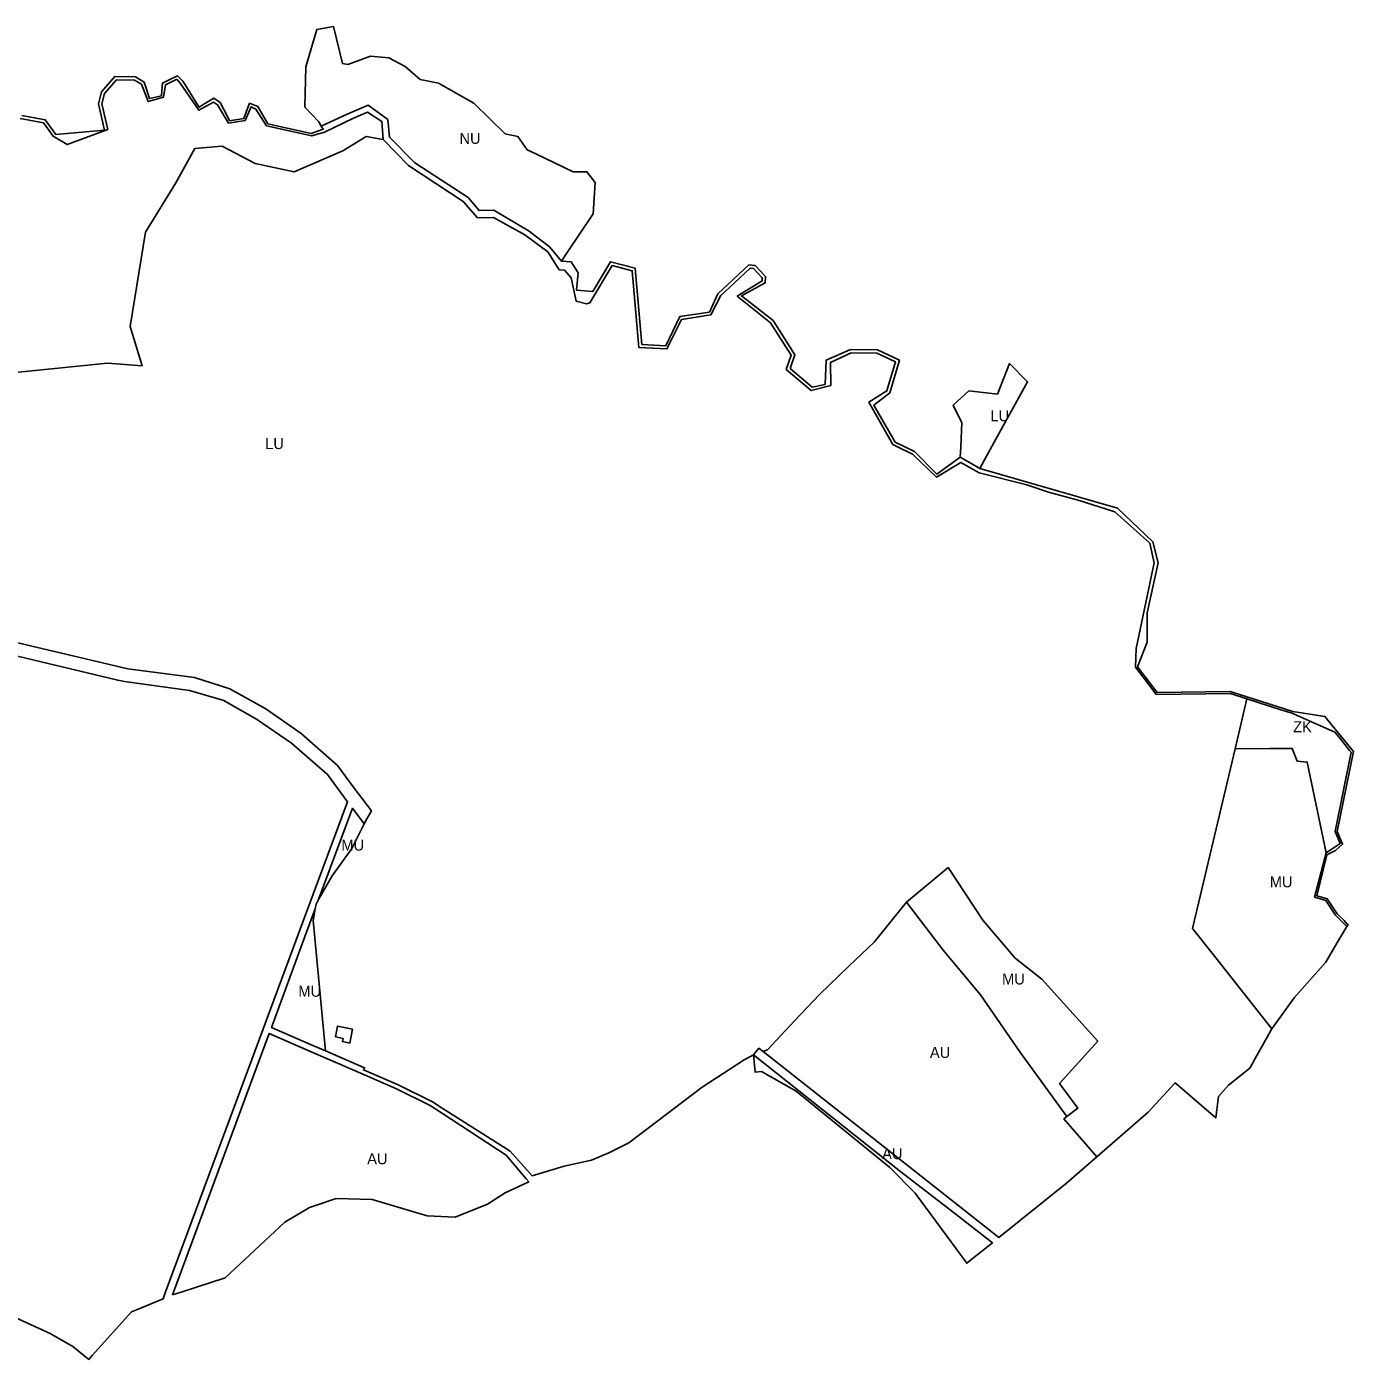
# Model space of a CAD drawing. Extents: x -522079 to -518833, y -1142398 to -1139961.
# Drawn here: x -519439 to -518833, y -1141872 to -1141262 of the extents above; entities that cross this region are included whole.
import ezdxf

# ---------------------------------------------------------------- set-up
doc = ezdxf.new("R2010")
doc.units = 0
for name, color, linetype in [('90640013', 7, 'Continuous'), ('90710013', 7, 'Continuous'), ('90730013', 7, 'Continuous'), ('90750013', 7, 'Continuous'), ('90770013', 7, 'Continuous'), ('90830013', 7, 'Continuous')]:
    doc.layers.add(name, color=color, linetype=linetype)

msp = doc.modelspace()

# ---------------------------------------------------------------- linework, layer by layer
at = {"layer": '90640013'}
msp.add_lwpolyline([(-519441.7, -1141302.87), (-519430.99, -1141304.77), (-519426.16, -1141311.48), (-519403.83, -1141309.49), (-519406.68, -1141297.5), (-519405.2, -1141292.02), (-519399.13, -1141285.07), (-519389.78, -1141285.13), (-519385.69, -1141287.55), (-519385.12, -1141289.38), (-519383.31, -1141295.11), (-519377.88, -1141293.85), (-519377.66, -1141291.53), (-519377.33, -1141288.06), (-519373.33, -1141286.11), (-519370.55, -1141284.76), (-519368.04, -1141287.17), (-519367.51, -1141288.01), (-519361.74, -1141297.24), (-519360.6, -1141299.07), (-519359.18, -1141298.18), (-519353.95, -1141294.93), (-519351.06, -1141296.96), (-519347.55, -1141303.63), (-519346.7, -1141305.23), (-519340.12, -1141304.19), (-519339.07, -1141301.4), (-519337.51, -1141297.26), (-519333.7, -1141298.67), (-519329.18, -1141306.68), (-519309.3, -1141311.02), (-519303.86, -1141309.05), (-519304.74, -1141307.68), (-519292.93, -1141302.27), (-519283.38, -1141298.07), (-519274.28, -1141304.73), (-519273.62, -1141312.83), (-519261.98, -1141324.54), (-519255.87, -1141328.5), (-519237.64, -1141340.3), (-519232.62, -1141346.31), (-519225.91, -1141346.11), (-519209.66, -1141355.81), (-519200.4, -1141362.91), (-519194.96, -1141369.43), (-519190.42, -1141369.81), (-519187.2, -1141374.82), (-519188.01, -1141382.78), (-519180.54, -1141383.29), (-519172.49, -1141369.75), (-519161.16, -1141372.68), (-519158.19, -1141407.51), (-519147.23, -1141408.12), (-519140.85, -1141394.82), (-519127.25, -1141392.73), (-519123.4, -1141384.39), (-519109.18, -1141371.2), (-519106.36, -1141371.37), (-519101.55, -1141376.47), (-519101.7, -1141379.43), (-519112.59, -1141385.36), (-519098.12, -1141396.65), (-519088.18, -1141412.32), (-519090.32, -1141418.48), (-519080.26, -1141427.02), (-519074.35, -1141425.83), (-519073.85, -1141414.66), (-519062.78, -1141409.81), (-519050.33, -1141409.98), (-519040.39, -1141414.74), (-519044.82, -1141429.69), (-519052, -1141435.32), (-519042.3, -1141452.19), (-519033.46, -1141456.53), (-519023.29, -1141466.86), (-519012.53, -1141459.04), (-519005.83, -1141462.95), (-519003.59, -1141464.2), (-518940.71, -1141482.48), (-518924.49, -1141497.8), (-518922.06, -1141507.35), (-518927.02, -1141530.23), (-518927.11, -1141543.74), (-518931.43, -1141555), (-518922.51, -1141566.63), (-518889.18, -1141566.18), (-518860.53, -1141575.36), (-518845.76, -1141577.71), (-518832.78, -1141593.74), (-518840.17, -1141630.23), (-518837.74, -1141636.08), (-518840.9, -1141638.87), (-518844.96, -1141640.98), (-518849.41, -1141659.71), (-518844.75, -1141661.05), (-518840.16, -1141667.91), (-518837.05, -1141671.02), (-518835.83, -1141672.48), (-518835.18, -1141672.79), (-518835.69, -1141673.66), (-518840.87, -1141668.48), (-518845.32, -1141661.82), (-518850.48, -1141660.34), (-518845.18, -1141639.97), (-518838.85, -1141635.75), (-518841.11, -1141630.32), (-518833.75, -1141593.98), (-518834.47, -1141593.24), (-518839.43, -1141586.95), (-518841.19, -1141584.77), (-518858.5, -1141577.22), (-518860.8, -1141576.22), (-518865.88, -1141574.59), (-518881.49, -1141569.59), (-518888.92, -1141567.21), (-518922.95, -1141567.54), (-518924.52, -1141565.49), (-518932.45, -1141555.15), (-518932.13, -1141546.59), (-518923.9, -1141507.34), (-518925.88, -1141498.42), (-518941.87, -1141484.11), (-518958.68, -1141478.71), (-518972.22, -1141475.1), (-518982.13, -1141471.67), (-519003.93, -1141466.26), (-519012.3, -1141461.46), (-519023.36, -1141468.17), (-519034.35, -1141457.76), (-519041.21, -1141454.39), (-519043.38, -1141453.33), (-519054.33, -1141433.88), (-519046.13, -1141428.81), (-519042.19, -1141415.54), (-519048.65, -1141412.42), (-519050.68, -1141411.48), (-519062.49, -1141411.31), (-519071.92, -1141415.76), (-519071.77, -1141426.39), (-519080.67, -1141428.64), (-519092.08, -1141418.96), (-519089.83, -1141412.51), (-519099.25, -1141397.67), (-519114.56, -1141385.44), (-519103.16, -1141378.52), (-519103.08, -1141377.03), (-519107.04, -1141372.83), (-519108.63, -1141372.74), (-519115.78, -1141379.37), (-519122.09, -1141385.22), (-519126.66, -1141393.95), (-519140.08, -1141396.13), (-519146.7, -1141409.56), (-519159.57, -1141408.94), (-519162.56, -1141373.86), (-519171.77, -1141371.48), (-519181.87, -1141388.46), (-519183.39, -1141388.93), (-519188.19, -1141387.74), (-519190.53, -1141377.07), (-519193.48, -1141373.59), (-519195.98, -1141373.38), (-519201.22, -1141365.24), (-519211.68, -1141357.48), (-519225.95, -1141349.55), (-519233.32, -1141349.64), (-519239.84, -1141342.13), (-519264.89, -1141325.79), (-519276.42, -1141313.78), (-519277.01, -1141305.57), (-519283.62, -1141301.34), (-519290.01, -1141304.08), (-519303.35, -1141310.46), (-519309.12, -1141312.18), (-519329.81, -1141307.56), (-519334.73, -1141299.89), (-519336.85, -1141298.85), (-519339.54, -1141305.07), (-519347.17, -1141306.35), (-519352.22, -1141297.98), (-519354, -1141296.72), (-519360.8, -1141300.45), (-519369.21, -1141288.13), (-519370.85, -1141286.3), (-519376.04, -1141288.86), (-519376.93, -1141294.5), (-519383.98, -1141296.49), (-519386.96, -1141288.54), (-519390.2, -1141286.63), (-519398.45, -1141286.57), (-519403.84, -1141292.74), (-519405.13, -1141297.52), (-519402.36, -1141309.19), (-519420.99, -1141316.12), (-519427.38, -1141312.36), (-519431.85, -1141306.14), (-519442.41, -1141304.27)], dxfattribs=at)
at = {"layer": '90710013'}
msp.add_lwpolyline([(-518845.18, -1141639.97), (-518853.84, -1141598.54), (-518858.42, -1141598.04), (-518860.72, -1141592.27), (-518870.9, -1141592.32), (-518886.88, -1141592.39), (-518881.49, -1141569.59), (-518865.88, -1141574.59), (-518860.8, -1141576.22), (-518858.5, -1141577.22), (-518841.19, -1141584.77), (-518839.43, -1141586.95), (-518834.47, -1141593.24), (-518833.75, -1141593.98), (-518841.11, -1141630.32), (-518838.85, -1141635.75)], close=True, dxfattribs=at)
at = {"layer": '90730013'}
msp.add_lwpolyline([(-519304.74, -1141307.68), (-519305.93, -1141305.82), (-519312.28, -1141299.01), (-519311.83, -1141280.54), (-519306.82, -1141263.47), (-519299.19, -1141262.23), (-519295.1, -1141279.15), (-519292.59, -1141279.53), (-519282.24, -1141275.71), (-519273.89, -1141276.5), (-519266.36, -1141280.43), (-519259.58, -1141286.33), (-519251.16, -1141288.07), (-519234.97, -1141297.23), (-519220.59, -1141311.22), (-519214.82, -1141312.52), (-519210.53, -1141318.6), (-519206.65, -1141320.44), (-519189.49, -1141328.56), (-519183.26, -1141328.59), (-519179.55, -1141333.52), (-519180.48, -1141347.87), (-519192.3, -1141365.49), (-519194.96, -1141369.43), (-519200.4, -1141362.91), (-519209.66, -1141355.81), (-519225.91, -1141346.11), (-519232.62, -1141346.31), (-519237.64, -1141340.3), (-519255.87, -1141328.5), (-519261.98, -1141324.54), (-519273.62, -1141312.83), (-519274.28, -1141304.73), (-519283.38, -1141298.07), (-519292.93, -1141302.27)], close=True, dxfattribs=at)
msp.add_lwpolyline([(-519442.41, -1141304.27), (-519431.85, -1141306.14), (-519427.38, -1141312.36), (-519420.99, -1141316.12), (-519402.36, -1141309.19), (-519405.13, -1141297.52), (-519403.84, -1141292.74), (-519398.45, -1141286.57), (-519390.2, -1141286.63), (-519386.96, -1141288.54), (-519383.98, -1141296.49), (-519376.93, -1141294.5), (-519376.04, -1141288.86), (-519370.85, -1141286.3), (-519369.21, -1141288.13), (-519360.8, -1141300.45), (-519354, -1141296.72), (-519352.22, -1141297.98), (-519347.17, -1141306.35), (-519339.54, -1141305.07), (-519336.85, -1141298.85), (-519334.73, -1141299.89), (-519329.81, -1141307.56), (-519309.12, -1141312.18), (-519303.35, -1141310.46), (-519290.01, -1141304.08), (-519283.62, -1141301.34), (-519277.01, -1141305.57), (-519276.42, -1141313.78), (-519284.21, -1141312.41), (-519294.89, -1141319.05), (-519317.19, -1141328.69), (-519334.98, -1141324.76), (-519350.02, -1141316.82), (-519362.63, -1141317.99), (-519371.28, -1141333.68), (-519385.2, -1141356.16), (-519392.16, -1141399.31), (-519386.73, -1141417.35), (-519402.53, -1141416.1), (-519450.75, -1141420.94)], dxfattribs=at)
at = {"layer": '90750013'}
msp.add_lwpolyline([(-519464.89, -1141545.09), (-519397.82, -1141561.07), (-519394.67, -1141561.74), (-519364.95, -1141565.79), (-519349.35, -1141570.28), (-519346.66, -1141571.83), (-519334.38, -1141578.92), (-519318.43, -1141589.84), (-519301.98, -1141604.24), (-519292.71, -1141616.64), (-519312.84, -1141670.86), (-519336.47, -1141734.52), (-519376.07, -1141841.19), (-519377.1, -1141843.96), (-519389.29, -1141849.01), (-519391.5, -1141849.93), (-519408.1, -1141868.36), (-519409.46, -1141869.87), (-519411.05, -1141871.62), (-519418.41, -1141865.69), (-519428.71, -1141859.77), (-519471.59, -1141840.28)], dxfattribs=at)
for points in [[(-519037.2, -1141662.52), (-519020.32, -1141684.47), (-519003.26, -1141704.92), (-518985.35, -1141731.05), (-518963.82, -1141760.65), (-518965.15, -1141761.66), (-518950.14, -1141779.05), (-518963.91, -1141791), (-518994.87, -1141815.89), (-519013.82, -1141800.95), (-519102.66, -1141730.9), (-519100.73, -1141730.04), (-519088.31, -1141716.77), (-519076.93, -1141704.76), (-519063.3, -1141691.75), (-519051.93, -1141680.89)], [(-519372.86, -1141842.19), (-519371.92, -1141839.65), (-519336.07, -1141742.78), (-519328.61, -1141722.63), (-519309.44, -1141730.94), (-519289.52, -1141739.58), (-519270.39, -1141747.88), (-519254.9, -1141755.61), (-519249.34, -1141759.14), (-519220.27, -1141778.33), (-519211, -1141789.08), (-519209.88, -1141790.38), (-519220.64, -1141795.43), (-519228.74, -1141800.67), (-519243.51, -1141806.68), (-519256.37, -1141806.05), (-519281.47, -1141798.57), (-519297.93, -1141798.04), (-519308.25, -1141801.56), (-519310.14, -1141802.21), (-519316.53, -1141805.97), (-519321.4, -1141808.82), (-519348.63, -1141834.32), (-519368.78, -1141840.86)], [(-519107.07, -1141732.42), (-519039.72, -1141785.92), (-519017.2, -1141803.32), (-518997.83, -1141818.27), (-519007.06, -1141825.69), (-519009.58, -1141827.71), (-519033.21, -1141795.69), (-519044.72, -1141783.93), (-519087.6, -1141748.94), (-519103.5, -1141739.96), (-519106.29, -1141740.33)]]:
    msp.add_lwpolyline(points, close=True, dxfattribs=at)
at = {"layer": '90770013'}
msp.add_lwpolyline([(-519450.75, -1141420.94), (-519402.53, -1141416.1), (-519386.73, -1141417.35), (-519392.16, -1141399.31), (-519385.2, -1141356.16), (-519371.28, -1141333.68), (-519362.63, -1141317.99), (-519350.02, -1141316.82), (-519334.98, -1141324.76), (-519317.19, -1141328.69), (-519294.89, -1141319.05), (-519284.21, -1141312.41), (-519276.42, -1141313.78), (-519264.89, -1141325.79), (-519239.84, -1141342.13), (-519233.32, -1141349.64), (-519225.95, -1141349.55), (-519211.68, -1141357.48), (-519201.22, -1141365.24), (-519195.98, -1141373.38), (-519193.48, -1141373.59), (-519190.53, -1141377.07), (-519188.19, -1141387.74), (-519183.39, -1141388.93), (-519181.87, -1141388.46), (-519171.77, -1141371.48), (-519162.56, -1141373.86), (-519159.57, -1141408.94), (-519146.7, -1141409.56), (-519140.08, -1141396.13), (-519126.66, -1141393.95), (-519122.09, -1141385.22), (-519115.78, -1141379.37), (-519108.63, -1141372.74), (-519107.04, -1141372.83), (-519103.08, -1141377.03), (-519103.16, -1141378.52), (-519114.56, -1141385.44), (-519099.25, -1141397.67), (-519089.83, -1141412.51), (-519092.08, -1141418.96), (-519080.67, -1141428.64), (-519071.77, -1141426.39), (-519071.92, -1141415.76), (-519062.49, -1141411.31), (-519050.68, -1141411.48), (-519048.65, -1141412.42), (-519042.19, -1141415.54), (-519046.13, -1141428.81), (-519054.33, -1141433.88), (-519043.38, -1141453.33), (-519041.21, -1141454.39), (-519034.35, -1141457.76), (-519023.36, -1141468.17), (-519012.3, -1141461.46), (-519003.93, -1141466.26), (-518982.13, -1141471.67), (-518972.22, -1141475.1), (-518958.68, -1141478.71), (-518941.87, -1141484.11), (-518925.88, -1141498.42), (-518923.9, -1141507.34), (-518932.13, -1141546.59), (-518932.45, -1141555.15), (-518924.52, -1141565.49), (-518922.95, -1141567.54), (-518888.92, -1141567.21), (-518881.49, -1141569.59), (-518886.88, -1141592.39), (-518906.3, -1141674.57), (-518897.41, -1141685.82), (-518869.99, -1141720.5), (-518876.08, -1141731.29), (-518880.1, -1141738.42), (-518889.83, -1141746.28), (-518894.38, -1141751.49), (-518895.73, -1141761.19), (-518914.26, -1141745.22), (-518926.6, -1141758.63), (-518950.14, -1141779.05), (-518965.15, -1141761.66), (-518963.82, -1141760.65), (-518958.75, -1141756.79), (-518967.09, -1141745.55), (-518949.63, -1141726.06), (-518975.25, -1141697.8), (-518987.45, -1141688.21), (-519002.22, -1141670.75), (-519018.14, -1141646.74), (-519037.2, -1141662.52), (-519051.93, -1141680.89), (-519063.3, -1141691.75), (-519076.93, -1141704.76), (-519088.31, -1141716.77), (-519100.73, -1141730.04), (-519102.66, -1141730.9), (-519104.58, -1141729.38), (-519107.07, -1141732.42), (-519111.34, -1141734.71), (-519130.56, -1141747.22), (-519164.17, -1141772.59), (-519173.18, -1141777.23), (-519181.21, -1141780.54), (-519193.63, -1141783.33), (-519208.31, -1141787.64), (-519218.36, -1141776.45), (-519249.47, -1141756.69), (-519253.85, -1141753.9), (-519269.54, -1141746.07), (-519285.49, -1141739.31), (-519284.96, -1141738.29), (-519302.86, -1141730.53), (-519308.5, -1141671.02), (-519307.53, -1141665.67), (-519307.13, -1141663.43), (-519305.95, -1141661.39), (-519299.72, -1141650.6), (-519290.81, -1141638.01), (-519285.15, -1141626.73), (-519283.88, -1141624.46), (-519281.83, -1141620.82), (-519286.19, -1141615.06), (-519289.76, -1141610.43), (-519297.36, -1141600.15), (-519313.9, -1141585.4), (-519330.14, -1141574.2), (-519346.5, -1141565.05), (-519362.75, -1141559.82), (-519393.2, -1141555.81), (-519465.6, -1141538.79)], dxfattribs=at)
for points in [[(-519012.53, -1141459.04), (-519012.34, -1141454.52), (-519011.87, -1141443.33), (-519015.74, -1141435.38), (-519008.63, -1141428.83), (-518995.53, -1141430.25), (-518989.97, -1141416.33), (-518981.74, -1141424.63), (-518994.55, -1141447.83), (-519001.41, -1141460.26), (-519003.59, -1141464.2), (-519005.83, -1141462.95)], [(-519291.74, -1141727), (-519290.41, -1141720.65), (-519297.27, -1141719.22), (-519298.29, -1141724.1), (-519294.81, -1141724.84), (-519295.11, -1141726.32)]]:
    msp.add_lwpolyline(points, close=True, dxfattribs=at)
at = {"layer": '90830013'}
for points in [[(-518845.18, -1141639.97), (-518850.48, -1141660.34), (-518845.32, -1141661.82), (-518840.87, -1141668.48), (-518835.69, -1141673.66), (-518840.27, -1141681.38), (-518845.39, -1141690.02), (-518852.72, -1141698.29), (-518859.88, -1141706.38), (-518869.99, -1141720.5), (-518897.41, -1141685.82), (-518906.3, -1141674.57), (-518886.88, -1141592.39), (-518870.9, -1141592.32), (-518860.72, -1141592.27), (-518858.42, -1141598.04), (-518853.84, -1141598.54)], [(-519305.95, -1141661.39), (-519290.49, -1141619.61), (-519285.15, -1141626.73), (-519290.81, -1141638.01), (-519299.72, -1141650.6)], [(-519037.2, -1141662.52), (-519018.14, -1141646.74), (-519002.22, -1141670.75), (-518987.45, -1141688.21), (-518975.25, -1141697.8), (-518949.63, -1141726.06), (-518967.09, -1141745.55), (-518958.75, -1141756.79), (-518963.82, -1141760.65), (-518985.35, -1141731.05), (-519003.26, -1141704.92), (-519020.32, -1141684.47)], [(-519302.86, -1141730.53), (-519309.63, -1141727.6), (-519327.57, -1141719.82), (-519312.39, -1141678.8), (-519307.53, -1141665.67), (-519308.5, -1141671.02)]]:
    msp.add_lwpolyline(points, close=True, dxfattribs=at)

# ---------------------------------------------------------------- texts
at = {"layer": '90710013'}
msp.add_text('ZK', height=5, rotation=0, dxfattribs=at).set_placement((-518860.315, -1141584.858))
at = {"layer": '90730013'}
msp.add_text('NU', height=5, rotation=0, dxfattribs=at).set_placement((-519241.561, -1141315.83))
at = {"layer": '90750013'}
for p in [(-519026.4, -1141733.797), (-519283.744, -1141782.41), (-519048.274, -1141780.065)]:
    msp.add_text('AU', height=5, rotation=0, dxfattribs=at).set_placement(p)
at = {"layer": '90770013'}
for rotation, p in [(360, (-518998.74, -1141442.662)), (0, (-519330.382, -1141455.38))]:
    msp.add_text('LU', height=5, rotation=rotation, dxfattribs=at).set_placement(p)
at = {"layer": '90830013'}
for rotation, p in [(0, (-519295.55, -1141638.996)), (0, (-518870.995, -1141655.775)), (360, (-518993.415, -1141700.221)), (0, (-519315.215, -1141705.806))]:
    msp.add_text('MU', height=5, rotation=rotation, dxfattribs=at).set_placement(p)

doc.saveas('drawing.dxf')
